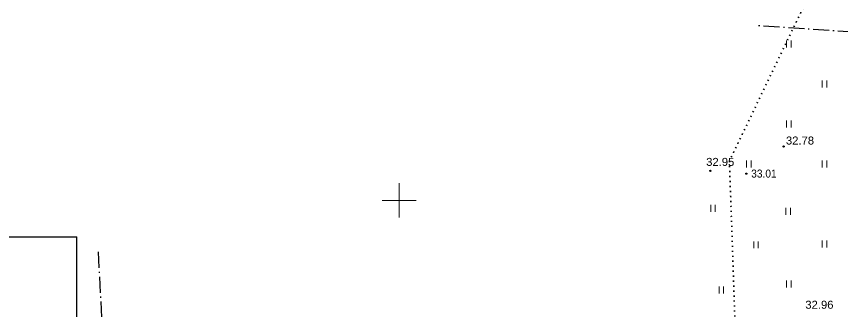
# Model space of a CAD drawing. Extents: x 380758 to 381729, y 283236 to 283533.
# Drawn here: x 381516.6 to 381588.6, y 283390.5 to 283416.1 of the extents above; entities that cross this region are included whole.
import ezdxf

# ---------------------------------------------------------------- set-up
doc = ezdxf.new("R2010")
doc.units = 0
doc.header["$LTSCALE"] = 0.28
doc.linetypes.add('DOT_DASHED', pattern=[7.7, 5, -1.2, 0.3, -1.2])
doc.linetypes.add('DOTTED', pattern=[1.5, 0.3, -1.2])
for name, color, linetype, lineweight in [('23', 7, 'Continuous', 13), ('25', 7, 'DOTTED', 35), ('29', 7, 'DOT_DASHED', 25), ('30', 7, 'Continuous', 13), ('40', 7, 'Continuous', 25), ('58', 7, 'Continuous', 25)]:
    doc.layers.add(name, color=color, linetype=linetype, lineweight=lineweight)

msp = doc.modelspace()

# ---------------------------------------------------------------- linework, layer by layer
at = {"layer": '23'}
for p, q in [((381583.867, 283413.382), (381583.867, 283413.982)), ((381584.267, 283413.382), (381584.267, 283413.982)), ((381586.967, 283409.882), (381586.967, 283410.482)), ((381587.367, 283409.882), (381587.367, 283410.482)), ((381583.867, 283406.382), (381583.867, 283406.982)), ((381584.267, 283406.382), (381584.267, 283406.982)), ((381580.367, 283402.882), (381580.367, 283403.482)), ((381580.767, 283402.882), (381580.767, 283403.482)), ((381586.967, 283402.882), (381586.967, 283403.482)), ((381587.367, 283402.882), (381587.367, 283403.482)), ((381577.23, 283399.002), (381577.23, 283399.602)), ((381577.63, 283399.002), (381577.63, 283399.602)), ((381583.791, 283398.743), (381583.791, 283399.343)), ((381584.191, 283398.743), (381584.191, 283399.343)), ((381580.985, 283395.806), (381580.985, 283396.406)), ((381581.385, 283395.806), (381581.385, 283396.406)), ((381586.967, 283395.882), (381586.967, 283396.482)), ((381587.367, 283395.882), (381587.367, 283396.482)), ((381583.867, 283392.382), (381583.867, 283392.982)), ((381584.267, 283392.382), (381584.267, 283392.982)), ((381577.96, 283391.87), (381577.96, 283392.47)), ((381578.36, 283391.87), (381578.36, 283392.47))]:
    msp.add_line(p, q, dxfattribs=at)
at = {"layer": '25'}
msp.add_lwpolyline([(381591.712, 283430.203), (381578.864, 283403.443), (381579.916, 283373.242), (381565.679, 283372.802), (381550.065, 283379.077), (381547.114, 283382.521), (381520.877, 283385.157), (381468.294, 283386.499)], dxfattribs=at)
at = {"layer": '29'}
msp.add_line((381611.421, 283413.279), (381581.171, 283415.285), dxfattribs=at)
msp.add_lwpolyline([(381523.679, 283395.486), (381525.074, 283370.24), (381487.74, 283369.088), (381474.487, 283377.297)], dxfattribs=at)
at = {"layer": '30'}
for points in [[(381550, 283401.5), (381550, 283400), (381550, 283398.5)], [(381548.5, 283400), (381550, 283400), (381551.5, 283400)]]:
    msp.add_lwpolyline(points, dxfattribs=at)
at = {"layer": '40'}
for p in [(381491.437, 283396.874), (381521.809, 283384.232)]:
    msp.add_line(p, (381521.839, 283396.802), dxfattribs=at)
at = {"layer": '58'}
for centre in [(381583.605, 283404.7141), (381577.204, 283402.5891), (381580.342, 283402.3351)]:
    msp.add_circle(centre, 0.0534, dxfattribs=at)

# ---------------------------------------------------------------- texts
for s, width, p in [('32.78', 1.05, (381583.804, 283404.884)), ('32.95', 1.05, (381576.834, 283403.015)), ('33.01', 0.95, (381580.768, 283401.993)), ('32.96', 1.05, (381585.5, 283390.522))]:
    msp.add_text(s, height=0.7, dxfattribs=dict(at, width=width)).set_placement(p)

doc.saveas('drawing.dxf')
